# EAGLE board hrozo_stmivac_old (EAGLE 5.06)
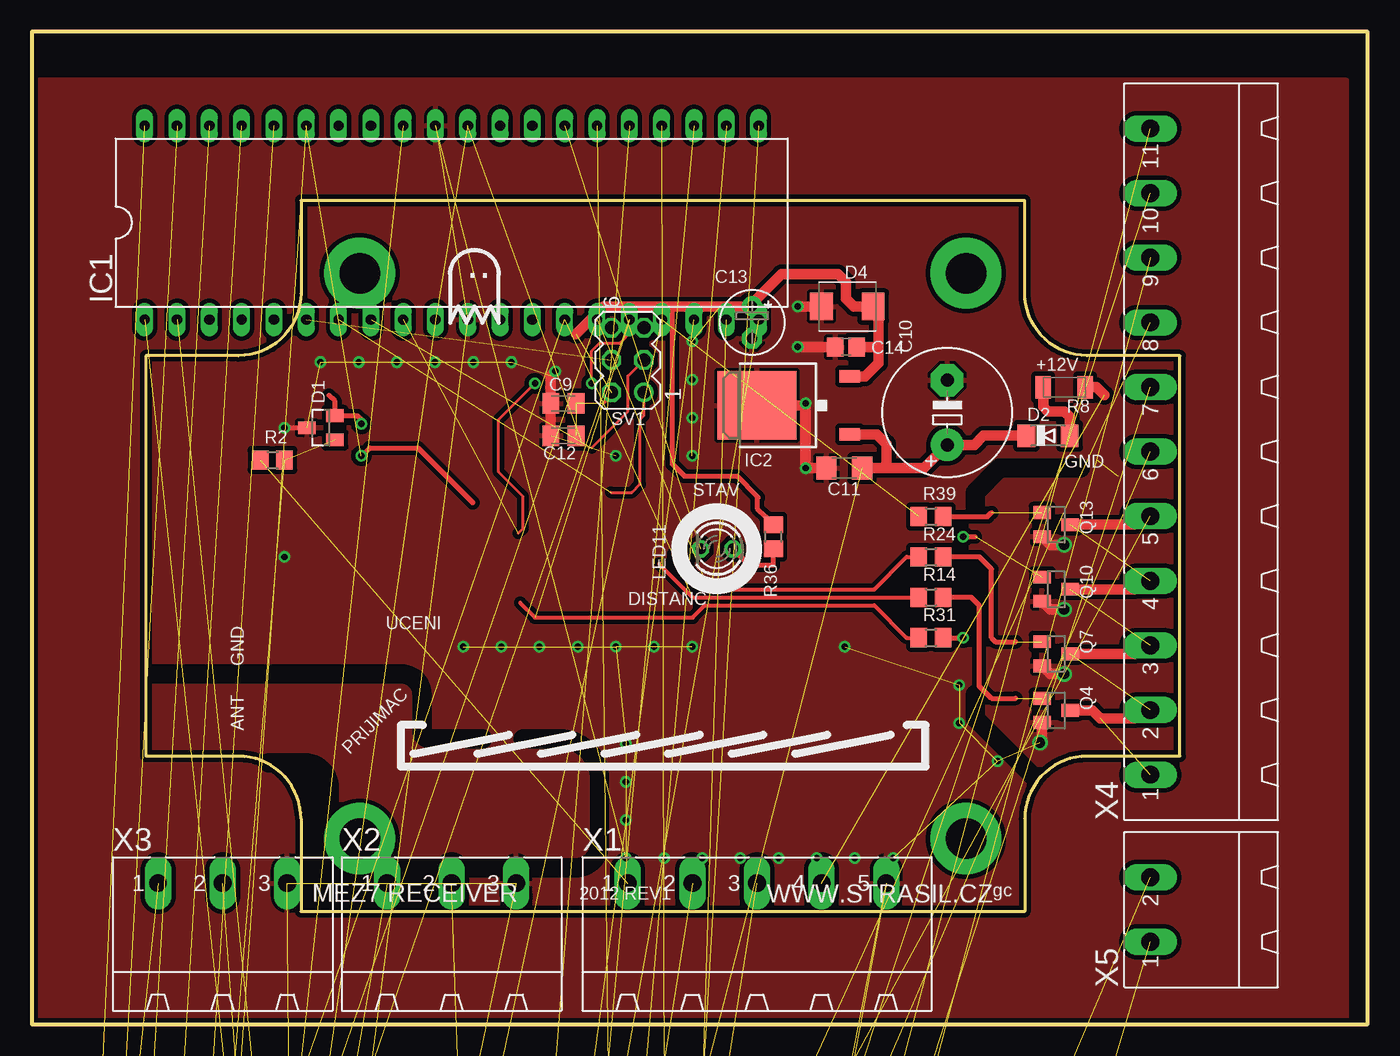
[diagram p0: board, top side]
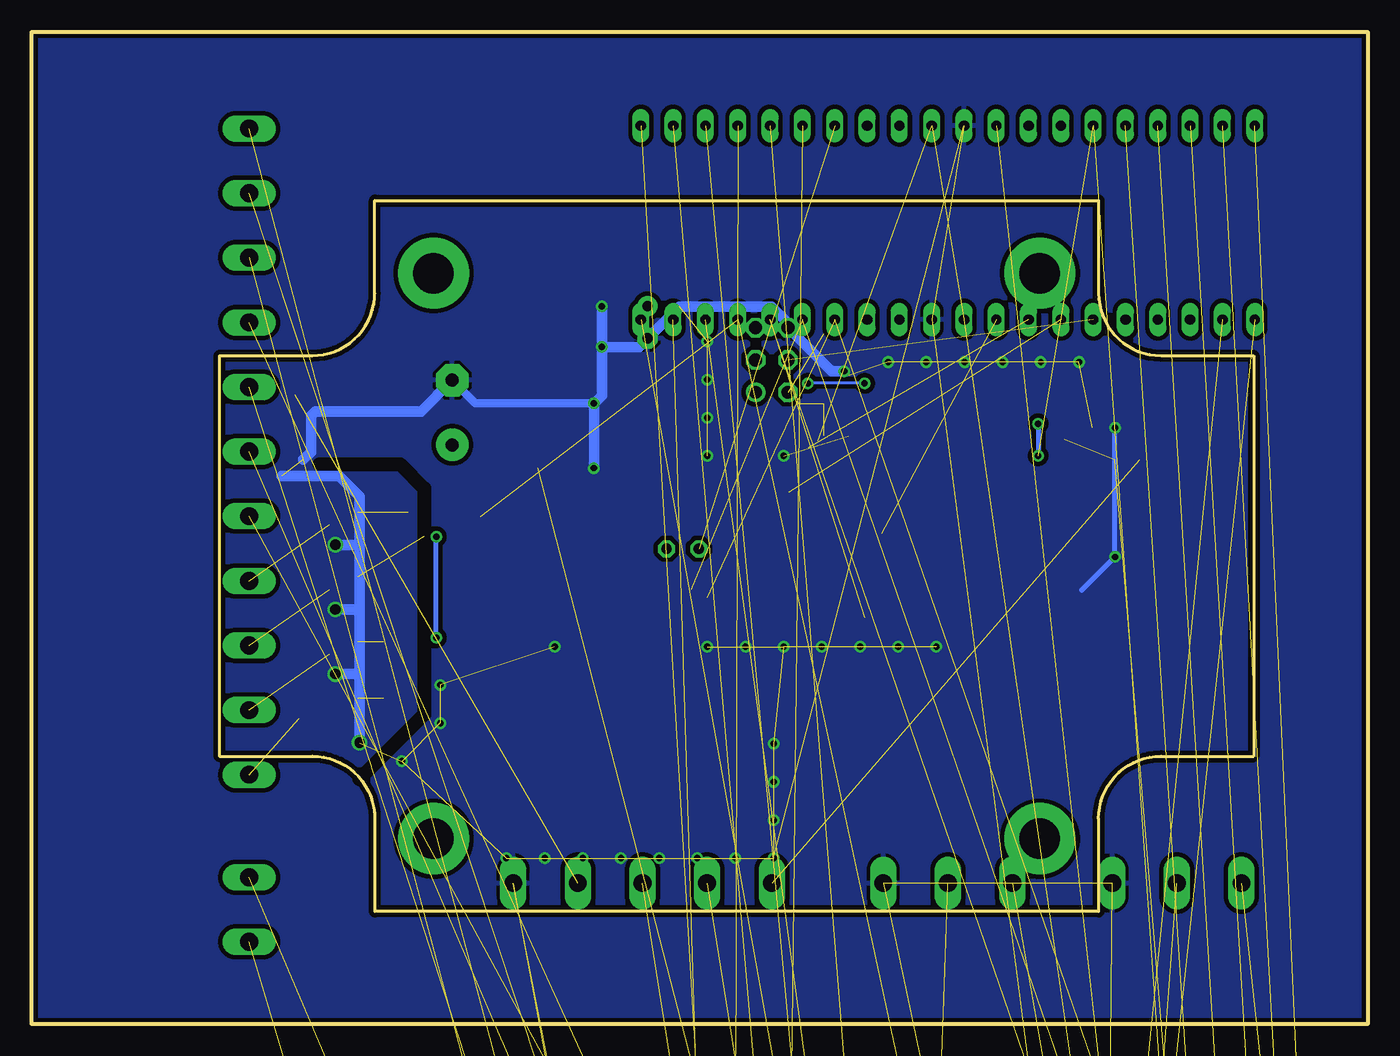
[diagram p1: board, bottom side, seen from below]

Size 105 x 78 mm. Coordinates in mm from the lower left corner, seen from the top.
Outline: 21.15,8.86 78.05,8.86 78.05,16.15 arc-90 82.95,21.05 90.24,21.05 90.24,52.55 82.95,52.55 arc-90 78.05,57.45 78.05,64.74 21.15,64.74 21.15,57.45 arc-90 16.25,52.55 8.96,52.55 8.96,21.05 16.25,21.05 arc-90 21.15,16.15 21.15,8.86
Outline: 0,0 105,0 105,78 0,78 0,0
Copper layers (1*16): Top 0.035mm / dielectric 1.5mm / Bottom 0.035mm
Design rules "default *": minimum track width 0.17mm, minimum drill 0.0102mm, track to track 0.2mm, track to pad 0.2mm, pad to pad 0.2mm, via to via 0.2mm, smd to smd 0.2mm, copper to edge 0.3mm, drill to drill 8mil, minimum pad ring 10mil, minimum via ring 8mil, stop-mask expansion 4mil, vias tented up to drill 0.6mm, thermal gap 10mil
Net classes: 2 ant: clearance 2 mm
tRestrict: 18 lines
bRestrict: 4 lines

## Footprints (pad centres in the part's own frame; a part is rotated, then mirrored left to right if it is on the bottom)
C0805K = smd 1.3 x 1.6: 1 -1,0; 2 1,0
E2,5-5 = drill 0.813 pad 1.6 round: + -1.27,0 | drill 0.813 pad 1.6 octagon: - 1.27,0
E5-10,5 = drill 1.016 pad 2.54 round: + -2.54,0 | drill 1.016 pad 2.54 octagon: - 2.54,0
C1206 = smd 1.6 x 1.8: 1 -1.4,0; 2 1.4,0
C0805 = smd 1.3 x 1.5: 1 -0.85,0; 2 0.85,0
SOT23 = smd 1 x 1.4: 1 -0.95,-1.1; 2 0.95,-1.1; 3 0,1.1
MINIMELF = smd 1.4 x 1.8: A 1.7,0; C -1.7,0
SMBJ = smd 1.78 x 2.16: A 2.04,0; C -2.03,0
DIL40 = drill 0.813 long: 1 -24.13,-7.62; 2 -21.59,-7.62; 3 -19.05,-7.62; 4 -16.51,-7.62; 5 -13.97,-7.62; 6 -11.43,-7.62; 7 -8.89,-7.62; 8 -6.35,-7.62; 9 -3.81,-7.62; 10 -1.27,-7.62; 11 1.27,-7.62; 12 3.81,-7.62; 13 6.35,-7.62; 14 8.89,-7.62; 15 11.43,-7.62; 16 13.97,-7.62; 17 16.51,-7.62; 18 19.05,-7.62; 19 21.59,-7.62; 20 24.13,-7.62; 21 24.13,7.62; 22 21.59,7.62; 23 19.05,7.62; 24 16.51,7.62; 25 13.97,7.62; 26 11.43,7.62; 27 8.89,7.62; 28 6.35,7.62; 29 3.81,7.62; 30 1.27,7.62; 31 -1.27,7.62; 32 -3.81,7.62; 33 -6.35,7.62; 34 -8.89,7.62; 35 -11.43,7.62; 36 -13.97,7.62; 37 -16.51,7.62; 38 -19.05,7.62; 39 -21.59,7.62; 40 -24.13,7.62
TO252 = smd 1 x 1.6: 1 -2.28,-4.8; 2 2.28,-4.8 | smd 5.4 x 6.2: 3 0,2.5
CHIPLED_0805 = smd 1.2 x 1.2: A 0,-1.05; C 0,1.05
LED3MM = drill 0.813 octagon: A -1.27,0; K 1.27,0
R0805 = smd 1.3 x 1.5: 1 -0.95,0; 2 0.95,0
M1206 = smd 1.6 x 2: 1 -1.4,0; 2 1.4,0
CA9V = drill 1.321 long: A -2.54,-5.08; E 2.54,-5.08; S 0,5.08
CT/CN1206 = smd 1.2 x 1.8: 1 -1.65,0; 2 1.65,0
MA03-2 = drill 1.016 round: 1 -2.54,-1.27 | drill 1.016 octagon: 2 -2.54,1.27; 3 0,-1.27; 4 0,1.27; 5 2.54,-1.27; 6 2.54,1.27
MSTBA5 = drill 1.397 long: 1 -10.16,5.08; 2 -5.08,5.08; 3 0,5.08; 4 5.08,5.08; 5 10.16,5.08
MSTBA3 = drill 1.397 long: 1 -5.08,5.08; 2 0,5.08; 3 5.08,5.08
MSTBA11 = drill 1.397 long: 1 -25.4,5.08; 2 -20.32,5.08; 3 -15.24,5.08; 4 -10.16,5.08; 5 -5.08,5.08; 6 0,5.08; 7 5.08,5.08; 8 10.16,5.08; 9 15.24,5.08; 10 20.32,5.08; 11 25.4,5.08
MSTBA2 = drill 1.397 long: 1 -2.54,5.08; 2 2.54,5.08

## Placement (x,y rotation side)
C1  100n  [C0805K]  not placed on the board
C2  100u  [E2,5-5]  not placed on the board
C3  100u  [E2,5-5]  not placed on the board
C4  100n  [C0805K]  not placed on the board
C5  100n  [C0805K]  not placed on the board
C6  100n  [C0805K]  not placed on the board
C7  100n  [C0805K]  not placed on the board
C8  100n  [C0805K]  not placed on the board
C9  100n  [C0805K]  41.78,48.78 180 top
C10  470u/16V  [E5-10,5]  71.96,48.07 90 top
C11  100n  [C1206]  63.86,43.7 180 top
C12  1n  [C0805K]  41.78,46.24 180 top
C13  100u  [E2,5-5]  56.61,55.17 270 top
C14  100n  [C0805]  64,53.23 0 top
D1  MMBZ9V1AL  [SOT23]  22.72,46.88 90 top
D2  LL4148  [MINIMELF]  79.88,46.24 0 top
D3  MMBZ9V1AL  [SOT23]  not placed on the board
D4  SMBJ 5V8  [SMBJ]  64.11,56.41 180 top
IC1  MEGA16-P  [DIL40]  33,63 0 top
IC2  78M05CDT  [TO252]  59.48,48.64 90 top
LED1  cervena  [CHIPLED_0805]  not placed on the board
LED2  cervena  [CHIPLED_0805]  not placed on the board
LED3  cervena  [CHIPLED_0805]  not placed on the board
LED4  cervena  [CHIPLED_0805]  not placed on the board
LED5  cervena  [CHIPLED_0805]  not placed on the board
LED6  cervena  [CHIPLED_0805]  not placed on the board
LED7  cervena  [CHIPLED_0805]  not placed on the board
LED8  cervena  [CHIPLED_0805]  not placed on the board
LED9  cervena  [CHIPLED_0805]  not placed on the board
LED10  cervena  [CHIPLED_0805]  not placed on the board
LED11  cervena  [LED3MM]  53.84,37.35 180 top
LED12  cervena  [CHIPLED_0805]  not placed on the board
LED13  cervena  [CHIPLED_0805]  not placed on the board
LED14  cervena  [CHIPLED_0805]  not placed on the board
Q1  IRLML0030  [SOT23]  not placed on the board
Q2  IRLML0030  [SOT23]  not placed on the board
Q3  IRLML0030  [SOT23]  not placed on the board
Q4  IRLML0030  [SOT23]  80.51,24.66 270 top
Q5  IRLML0030  [SOT23]  not placed on the board
Q6  IRLML0030  [SOT23]  not placed on the board
Q7  IRLML0030  [SOT23]  80.51,29.1 270 top
Q8  IRLML0030  [SOT23]  not placed on the board
Q9  IRLML0030  [SOT23]  not placed on the board
Q10  IRLML0030  [SOT23]  80.51,34.18 270 top
Q11  IRLML0030  [SOT23]  not placed on the board
Q12  IRLML0030  [SOT23]  not placed on the board
Q13  IRLML0030  [SOT23]  80.51,39.26 270 top
R1  10k  [R0805]  not placed on the board
R2  1k  [R0805]  18.92,44.34 0 top
R3  22k  [R0805]  not placed on the board
R4  2R2  [M1206]  not placed on the board
R5  2R2  [M1206]  not placed on the board
R6  10k  [CA9V]  not placed on the board
R7  1k  [R0805]  not placed on the board
R8  SN035  [CT/CN1206]  81.15,50.05 180 top
R9  1k  [R0805]  not placed on the board
R10  10k  [CA9V]  not placed on the board
R11  10k  [R0805]  not placed on the board
R12  1k  [R0805]  not placed on the board
R13  1k  [R0805]  not placed on the board
R14  1k  [R0805]  70.67,33.55 0 top
R15  1k  [R0805]  not placed on the board
R16  1k  [R0805]  not placed on the board
R17  1k  [R0805]  not placed on the board
R18  1k  [R0805]  not placed on the board
R19  10k  [CA9V]  not placed on the board
R20  1k  [R0805]  not placed on the board
R21  10k  [R0805]  not placed on the board
R22  1k  [R0805]  not placed on the board
R23  1k  [R0805]  not placed on the board
R24  1k  [R0805]  70.67,36.72 0 top
R25  1k  [R0805]  not placed on the board
R26  1k  [R0805]  not placed on the board
R27  1k  [R0805]  not placed on the board
R28  10k  [CA9V]  not placed on the board
R29  1k  [R0805]  not placed on the board
R30  1k  [R0805]  not placed on the board
R31  1k  [R0805]  70.67,30.37 0 top
R32  1k  [R0805]  not placed on the board
R33  1k  [R0805]  not placed on the board
R34  1k  [R0805]  not placed on the board
R35  10k  [CA9V]  not placed on the board
R36  470  [R0805]  58.28,38.31 90 top
R37  1k  [R0805]  not placed on the board
R38  1k  [R0805]  not placed on the board
R39  1k  [R0805]  70.67,39.9 0 top
R40  1k  [R0805]  not placed on the board
R41  1k  [R0805]  not placed on the board
R42  1k  [R0805]  not placed on the board
SV1  [MA03-2]  46.84,52.2 90 top
U$1  [BUBAK]  34.16,57.67 0 top
X1  MSTBA5  [MSTBA5]  57,6 0 top
X2  MSTBA3  [MSTBA3]  33,6 0 top
X3  MSTBA3  [MSTBA3]  15,6 0 top
X4  MSTBA11  [MSTBA11]  93,45 90 top
X5  MSTBA2  [MSTBA2]  93,9 90 top

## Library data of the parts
C1-C14 R1-R5 R7 R9 R11-R18 R20-R27 R29-R34 R36-R42 = rcl
D1-D4 = diode
IC1 = atmel
IC2 = linear
LED1-LED14 = led
Q1-Q13 = transistor-small-signal
R6 R10 R19 R28 R35 = pot
R8 = varistor
SV1 = con-lstb
U$1 = komp
X1-X5 = con-phoenix-508

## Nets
+5V: C9.1 C12.1 C13.+ C14.2 D4.C IC1.10 IC1.30 IC2.2 R1.1 R6.E R10.E R11.1 R19.E R21.1 R28.E R35.E R36.2 SV1.2 X1.2
+12V: C10.+ C11.1 D2.C IC2.1 R4.2 R5.2
AD1: IC1.40 R35.S
AD2: IC1.39 R28.S
AD3: IC1.38 R19.S
AD4: IC1.37 R10.S
AD5: IC1.36 R6.S
GND: C1.2 C2.- C3.- C4.2 C5.2 C6.2 C7.1 C8.2 C9.2 C10.- C11.2 C12.2 C13.- C14.1 D1.3 D3.3 D4.A IC1.11 IC1.31 IC2.3 LED1.C LED2.C LED3.C LED4.C LED5.C LED6.C LED7.C LED8.C LED9.C LED10.C LED13.C LED14.C Q1.2 Q2.2 Q3.2 Q4.2 Q5.2 Q6.2 Q7.2 Q8.2 Q9.2 Q10.2 Q11.2 Q12.2 Q13.2 R3.1 R6.A R10.A R19.A R28.A R35.A R42.1 SV1.6 X1.5 X2.3 X3.3
IN1: C1.1 D1.1 R1.2 R2.2
INF: D1.2 IC1.35 R3.2 X1.3
INS1: C6.1 D3.1 IC1.1 R11.2 R15.2
INS2: C7.2 D3.2 IC1.2 R20.2 R21.2
LED_SIGN: IC1.27 LED11.K
MISO: IC1.7 SV1.1
MOSI: IC1.6 SV1.4
N$1: R8.1 X1.4
N$2: Q4.3 X4.1
N$3: Q4.1 R14.2
N$4: Q7.1 R24.2
N$5: Q10.1 R31.2
N$6: Q13.1 R39.2
N$7: Q7.3 X4.2
N$8: Q10.3 X4.3
N$9: Q13.3 X4.4
N$10: R2.1 X1.1
N$11: R15.1 X3.2
N$12: R20.1 X2.2
N$13: LED7.A R27.1
N$15: D2.A R8.2
N$16: C8.1 IC1.32
N$17: LED4.A R18.1
N$18: Q2.3 X4.5
N$19: Q2.1 R12.2
N$20: Q5.1 R22.2
N$21: Q8.1 R29.2
N$22: Q11.1 R37.2
N$23: Q5.3 X4.6
N$24: Q8.3 X4.7
N$25: Q11.3 X4.8
N$26: Q3.3 X4.10
N$27: Q3.1 R13.2
N$28: Q6.1 R23.2
N$29: Q9.1 R30.2
N$30: Q12.1 R38.2
N$31: Q6.3 X4.11
N$32: Q9.3 X5.1
N$33: Q12.3 X5.2
N$34: Q1.3 X4.9
N$35: Q1.1 R7.2
N$36: LED10.A R34.1
N$37: LED2.A R16.1
N$38: C2.+ C4.1 R4.1 X2.1
N$39: C3.+ C5.1 R5.1 X3.1
N$41: LED5.A R25.1
N$42: LED8.A R32.1
N$43: LED13.A R40.1
N$44: LED1.A R9.1
N$45: LED3.A R17.1
N$46: LED6.A R26.1
N$47: LED9.A R33.1
N$50: LED14.A R41.1
N$51: LED12.C R42.2
N$56: LED11.A R36.1
OUT1: IC1.14 R14.1 R18.2
OUT2: IC1.15 R24.1 R27.2
OUT3: IC1.16 R31.1 R34.2
OUT4: IC1.17 LED12.A R39.1
OUT5: IC1.18 R12.1 R16.2
OUT6: IC1.19 R22.1 R25.2
OUT7: IC1.20 R29.1 R32.2
OUT8: IC1.21 R37.1 R40.2
OUT9: IC1.22 R7.1 R9.2
OUT10: IC1.23 R13.1 R17.2
OUT11: IC1.24 R23.1 R26.2
OUT12: IC1.25 R30.1 R33.2
OUT13: IC1.26 R38.1 R41.2
RESET: IC1.9 SV1.5
SCK: IC1.8 SV1.3

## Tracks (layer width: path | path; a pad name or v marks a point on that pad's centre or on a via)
+5V  (14 unrouted)
  Top 0.254: 44.95,48.78 45.57,49.4 SV1.2
  Top 0.406: C12.1 43.19,45.83 | 57.02,41.48 57.02,40.53 57.65,39.9 R36.2 | 57.02,41.48 57.11,41.39 | 57.02,41.48 55.43,43.07 51.3,43.07 50.35,44.02 50.35,56.09 50.67,56.41
  Top 0.813: IC2.2 65.5,50.92 66.54,51.96 66.54,53.23 | 66.54,53.23 C14.2 | 66.54,53.23 66.54,56 D4.C 64.64,56.41 64,57.04 64,58.31 63.36,58.94 58.92,58.94 56.61,56.64 C13.+ 56.57,56.41 50.67,56.41 44.95,56.41 42.78,54.23
+12V  (2 unrouted)
  Top 0.813: D2.C 74.79,46.24 74.08,45.53 C10.+ 70.12,43.7 67.18,43.7 | C11.1 67.18,43.7 | IC2.1 66.43,46.36 67.18,45.61 67.18,43.7
AD1  (1 unrouted)
AD2  (1 unrouted)
AD3  (1 unrouted)
AD4  (1 unrouted)
AD5  (1 unrouted)
GND  (via drill 0.5, 0.8)  (77 unrouted)
  Top 0.406: C12.2 40.8,46.23 | v19.87,46.88 D1.3
  Top 0.813: C11.2 v60.83,43.7 v60.83,48.78 60.68,48.64 IC2.3 | v60.19,56.41 D4.A | v60.19,53.23 C14.1 | v41.14,51.33 40.78,50.96 C9.2 C12.2 | Q4.2 79.41,22.29 v79.24,22.11 | Q7.2 80.05,27.51 v81.15,27.51 | Q10.2 80.05,32.59 v81.15,32.59 | Q13.2 80.05,37.67 v81.15,37.67
  Bottom 0.406: v19.87,46.88 v19.87,36.72 22.48,34.1
  Bottom 0.61: C10.- 70.13,48.78 v60.83,48.78
  Bottom 0.813: v60.83,43.7 v60.83,48.78 60.19,49.42 v60.19,53.23 | v60.19,53.23 v60.19,56.41 | v60.19,53.23 57.28,53.23 C13.- 54.11,56.41 46.86,56.41 45.57,55.12 SV1.6 42.15,51.33 v41.14,51.33 | v79.24,22.11 79.24,27.51 | 79.24,27.51 79.24,32.27 | 79.24,32.27 79.24,37.67 | 79.24,37.67 79.24,41.48 80.83,43.07 85.37,43.07 | 79.24,37.67 v81.15,37.67 | v81.15,32.59 79.56,32.59 79.24,32.27 | 79.24,27.51 v81.15,27.51 | C10.- 74.42,48.15 82.73,48.15 83.05,47.83 83.05,44.98 83.66,44.37
  other vias: 45.9,44.66 51.9,44.66 51.9,47.66 51.9,50.66 51.9,53.66 33.9,29.66 36.9,29.66 39.9,29.66 42.9,29.66 45.9,29.66 51.9,29.66 48.9,29.66 63.9,29.66 72.9,26.66 72.9,23.66 75.9,20.66 46.69,13.04 49.69,13.04 52.69,13.04 55.69,13.04 58.69,13.04 61.69,13.04 64.69,13.04 67.69,13.04 46.69,16.04 46.69,19.04 46.69,22.04 25.69,52.04 28.69,52.04 31.69,52.04 34.69,52.04 37.69,52.04 22.69,52.04
  pour Top (isolate 0.35): -6.17,74.19 -6.17,-0.11 103.37,-0.11 103.37,74.19
  pour Bottom (isolate 0.35): -17.6,100.54 -17.6,-2.33 130.04,-2.33 130.04,100.54
IN1  (3 unrouted)
INF  (via drill 0.5)  (3 unrouted)
  Top 0.406: 23.36,49.42 23.83,48.95 D1.2 25.58,47.83 25.9,47.52 v25.9,47.2 | 34.67,40.97 30.34,45.29 26.53,45.29 v25.9,44.66
  Bottom 0.406: v25.9,47.2 v25.9,44.66
INS1  (4 unrouted)
INS2  (4 unrouted)
LED_SIGN  (1 unrouted)
  Top 0.305: LED11.K 52.15,37.77
MISO  (1 unrouted)
  Top 0.254: 45.52,41.8 47.17,41.8 47.81,42.44 47.81,47.52 48.11,47.81 SV1.1
MOSI  (1 unrouted)
N$1  (1 unrouted)
  Top 0.813: 84.29,49.45 83.69,50.05 R8.1
N$2  (1 unrouted)
  Top 0.813: Q4.3 83.37,24.66 84,24.02 86.64,24.02
N$3  (1 unrouted)
  Top 0.406: 77.33,25.61 75.43,25.61 74.48,26.56 74.48,32.91 73.84,33.55 R14.2
N$4  (1 unrouted)
  Top 0.406: 77.33,30.05 75.75,30.05 75.43,30.37 75.43,35.77 74.48,36.72 R24.2
N$5  (via drill 0.5)  (1 unrouted)
  Top 0.406: v73.21,38.31 74.16,38.31 | R31.2 v73.21,30.37
  Bottom 0.406: v73.21,30.37 v73.21,38.31
N$6  (1 unrouted)
  Top 0.406: R39.2 75.11,39.9 75.43,40.21
N$7  (1 unrouted)
  Top 0.813: Q7.3 86.64,29.1
N$8  (1 unrouted)
  Top 0.813: Q10.3 86.64,34.18
N$9  (1 unrouted)
  Top 0.813: Q13.3 86.64,39.26
N$10  (1 unrouted)
N$11  (1 unrouted)
N$12  (1 unrouted)
N$13  (1 unrouted)
N$14  (via drill 3.17 pad 5.59)
  other vias: 73.43,59.03
N$15
  Top 0.813: R8.2 79.5,48.53 79.88,48.15 81.15,48.15 81.57,47.72 D2.A
N$16  (1 unrouted)
N$17  (1 unrouted)
N$18  (1 unrouted)
N$19  (1 unrouted)
N$20  (1 unrouted)
N$21  (1 unrouted)
N$22  (1 unrouted)
N$23  (1 unrouted)
N$24  (1 unrouted)
N$25  (1 unrouted)
N$26  (1 unrouted)
N$27  (1 unrouted)
N$28  (1 unrouted)
N$29  (1 unrouted)
N$30  (1 unrouted)
N$31  (1 unrouted)
N$32  (1 unrouted)
N$33  (1 unrouted)
N$34  (1 unrouted)
N$35  (1 unrouted)
N$36  (1 unrouted)
N$37  (1 unrouted)
N$38  (3 unrouted)
N$39  (3 unrouted)
N$40  (via drill 3.17 pad 5.59)
  other vias: 73.43,14.57
N$41  (1 unrouted)
N$42  (1 unrouted)
N$43  (1 unrouted)
N$44  (1 unrouted)
N$45  (1 unrouted)
N$46  (1 unrouted)
N$47  (1 unrouted)
N$48  (via drill 3.17 pad 5.59)
  other vias: 25.77,14.57
N$49  (via drill 3.17 pad 5.59)
  other vias: 25.77,59.03
N$50  (1 unrouted)
N$51  (1 unrouted)
N$56
  Top 0.406: LED11.A 56.38,36.09 58.28,36.09 R36.1
OUT1  (2 unrouted)
  Top 0.305: R14.1 51.94,33.55 49.31,36.17
OUT2  (2 unrouted)
  Top 0.305: R24.1 68.76,36.72 66.22,34.18 53.2,34.18 50.41,36.97
OUT3  (2 unrouted)
  Top 0.305: 38.39,33.12 39.55,31.96 51.94,31.96 52.89,32.91 66.22,32.91 68.76,30.37 R31.1 70.03,30.37
OUT4  (2 unrouted)
OUT5  (2 unrouted)
OUT6  (2 unrouted)
OUT7  (2 unrouted)
OUT8  (2 unrouted)
OUT9  (2 unrouted)
OUT10  (2 unrouted)
OUT11  (2 unrouted)
OUT12  (2 unrouted)
OUT13  (2 unrouted)
RESET  (via drill 0.5)  (1 unrouted)
  Top 0.254: SV1.5 47.87,54.5 47.17,54.5 46.22,53.55 44.63,53.55 44,52.91 v44,50.37 | v39.55,50.37 36.69,47.52 36.69,43.39 38.6,41.48 38.6,38.94 38.23,38.57
  Bottom 0.254: v39.55,50.37 v44,50.37
SCK  (1 unrouted)
  Top 0.254: SV1.3 46.86,50.95 46.86,48.15 44,45.29

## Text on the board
tPlace: +12V | GND | STAV | DISTANC | UCENI | GND | ANT | PRIJIMAC | MEZ7 RECEIVER | 2012 REV1 | WWW.STRASIL.CZ | gc
Document: KRABICKA S3A-352510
